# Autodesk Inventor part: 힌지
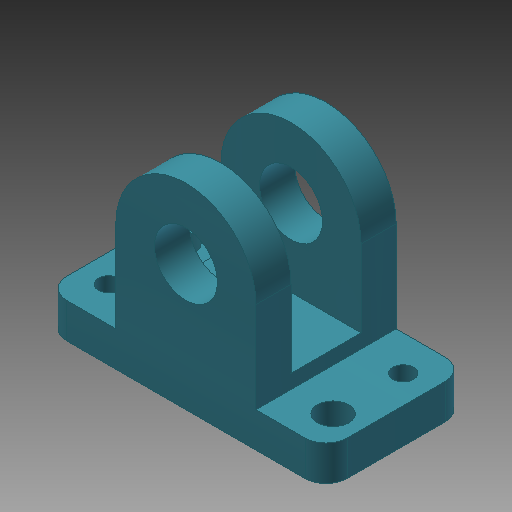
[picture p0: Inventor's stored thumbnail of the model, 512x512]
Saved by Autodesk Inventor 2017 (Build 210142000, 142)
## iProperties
Created: 2019-09
Part Number: 힌지
Material: 알루미늄 6061
Document SubType Name: Modeling
Designer: mduedu
Density: 1 g/cm^3
Appearance: 커뎃 파란색
Author: mduedu
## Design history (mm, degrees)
sketch "스케치1"
  geometry: L1 (-20, 0)-(20, 0); L2 (20, 0)-(20, 5); L3 (-20, 5)-(-20, 0); L4 (10, 5)-(10, 18); L5 (-10, 18)-(-10, 5); L6 (20, 5)-(10, 5); L7 (-10, 5)-(-20, 5); C1 r 4.5 at (0, 18); A1 r 10 centre (0, 18) between (10, 18) and (-10, 18); 2 further points
  constraints: 14 end point, 4 parallel, 2 centre point, 2 coincident, 2 point on circle, 2 tangent, 1 collinear, 1 horizontal, 1 midpoint, 1 perpendicular, 1 vertical, 1 vertical alignment
  dimensions: "d0" = 40 distance of L1.start L1.end; "d2" = 20 distance between parallel lines of L4 L5; "d3" = 18 distance from line of L1 A1.centre; "d4" = 5 distance of L1.end L2.end; "d5" = 9 diameter of C1
extrude "돌출1" new body sketch "스케치1" stored distance "d6" = 20; taper "d7" = 0 deg
sketch "스케치2"
  geometry: L1 (7, 5)-(37, 5); L2 (37, 5)-(37, -5); L3 (37, -5)-(7, -5); L4 (7, -5)-(7, 5); L5 (0, 10)-(0, -10) reference; 2 further points
  constraints: 8 end point, 2 parallel, 1 horizontal, 1 horizontal alignment, 1 midpoint, 1 perpendicular
  dimensions: "d8" = 7 distance between parallel lines of L5 L4; "d9" = 10 distance of L1.end L2.end; "d10" = 30 distance of L2.end L3.end
extrude "돌출2" cut sketch "스케치2" stored distance "d11" = 20; taper "d12" = 0 deg
sketch "스케치3"
  geometry: 3 further points
  dimensions: "d13" = 16 horizontal distance of point (6, 15) point (-10, 10); "d14" = 32 horizontal distance of point (-26, 5) point (6, 15); "d15" = 5 vertical distance of point (6, 15) point (-10, 10); "d16" = 10 vertical distance of point (-26, 5) point (6, 15)
hole "구멍1" sketch "스케치3" at (6, 15), (-26, 5) diameter "d17" = 3; stored, may be unused: countersink angle "d21" = 90 deg, drill point angle "d23" = 118 deg; dims "d18" = 6, "d19" = 4, "d20" = 2, "d22" = 8
sketch "스케치4"
  geometry: C1 r 1.5 at (6, 15) reference; C2 r 1.5 at (-26, 5) reference; 3 further points
  constraints: 2 horizontal alignment, 2 vertical alignment
hole "구멍2" sketch "스케치4" at (-26, 15), (6, 5) diameter "d24" = 4.5; stored, may be unused: countersink angle "d28" = 90 deg, drill point angle "d30" = 118 deg; dims "d25" = 6, "d26" = 4, "d27" = 2, "d29" = 8
fillet "모깎기1" dims "d31" = 3
node "솔리드1"
